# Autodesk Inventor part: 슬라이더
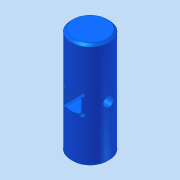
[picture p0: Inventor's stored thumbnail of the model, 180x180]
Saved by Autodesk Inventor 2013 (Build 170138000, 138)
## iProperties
Company: 한국ATC센터
Created: 2015-04
Part Number: 슬라이더
Document SubType Name: Modeling
Designer: KYOUNG IL JANG
Density: 1 g/cm^3
Material: 강철
Mass: 11.2119 g
Surface Area: 38.892 cm^2
Volume: 11.2119 cm^3
Author: KYOUNG IL JANG
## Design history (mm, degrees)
sketch "스케치1"
  geometry: C1 r 9 at (0, 0); 1 further point
  constraints: 1 centre point, 1 coincident
  dimensions: "d0" = 18 diameter of C1
extrude "돌출1" new body sketch "스케치1" stored distance "d1" = 50; taper "d2" = 0 deg
node "작업 평면1"
sketch "스케치3"
  geometry: L1 (4, 25)-(-4, 25); L2 (-4, 25)-(-4, -25); L3 (-4, -25)-(4, -25); L4 (4, -25)-(4, 25); 3 further points
  constraints: 8 end point, 2 midpoint, 2 parallel, 1 horizontal, 1 horizontal alignment, 1 perpendicular, 1 vertical alignment
  dimensions: "d5" = 8 distance of L1.start L1.end; "d6" = 50 distance of L1.end L2.end
extrude "돌출3" cut sketch "스케치3" stored distance "d7" = 8; taper "d8" = 0 deg
sketch "스케치4"
  geometry: 5 further points
hole "구멍1" sketch "스케치4" at (4, 4), (-4, 4), (-4, -4), (4, -4) diameter "d9" = 2; stored, may be unused: countersink angle "d13" = 90 deg, drill point angle "d15" = 118 deg; dims "d10" = 6, "d11" = 4, "d12" = 2, "d14" = 8
node "작업 평면2"
sketch "스케치5"
  geometry: 1 further point
hole "구멍2" sketch "스케치5" at (0, 0) diameter "d16" = 5; stored, may be unused: countersink angle "d20" = 90 deg, drill point angle "d22" = 118 deg; dims "d17" = 6, "d18" = 4, "d19" = 2, "d21" = 8
chamfer "모따기1" distance "d23" = 1; stored, may be unused: second distance "d24" = 2, angle "d25" = 45 deg
node "솔리드1"
mirror "대칭1"
